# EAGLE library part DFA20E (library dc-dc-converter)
DFA20 Single-Output DC-DC Series Source: www.power-one.com / dfa20s_PCB mountable.pdf
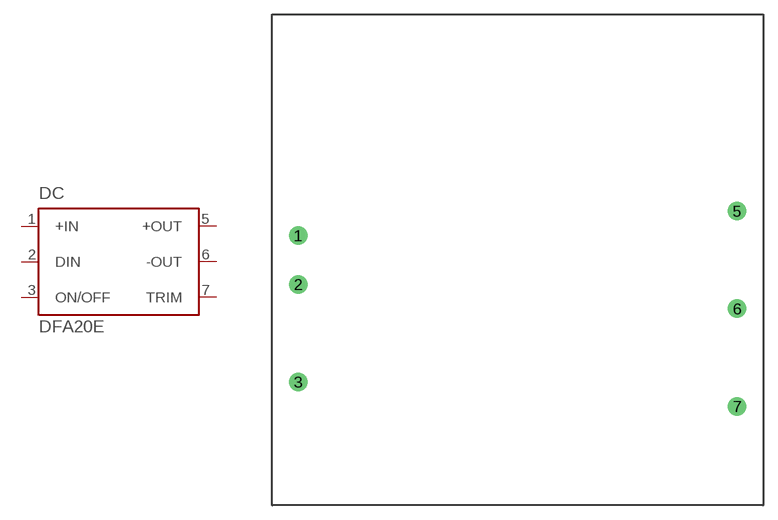
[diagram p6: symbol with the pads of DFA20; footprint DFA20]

Designator prefix DC

## DFA20E12S3.3 (OC_FARNELL: unknown; OC_NEWARK: unknown), DFA20E12S5 (OC_FARNELL: unknown; OC_NEWARK: unknown), DFA20E12S12 (OC_FARNELL: unknown; OC_NEWARK: unknown), DFA20E12S15 (OC_FARNELL: unknown; OC_NEWARK: unknown), DFA20E24S3.3 (OC_FARNELL: unknown; OC_NEWARK: unknown), DFA20E24S5 (OC_FARNELL: unknown; OC_NEWARK: unknown), DFA20E24S12 (OC_FARNELL: unknown; OC_NEWARK: unknown), DFA20E24S15 (OC_FARNELL: unknown; OC_NEWARK: unknown), DFA20E48S12 (OC_FARNELL: unknown; OC_NEWARK: unknown)  [DFA20]
1  +IN  in
2  DIN  in
3  ON/OFF  in
5  +OUT  out
6  -OUT  out
7  TRIM  in

## Footprint DFA20 (pad centres in mm)
DFA20 Single-Output DC-DC Series Source: www.power-one.com / dfa20s_PCB mountable.pdf
drill 1.2 pad 1.93 round: 1 -22.86,2.54; 2 -22.86,-2.54; 3 -22.86,-12.7; 5 22.86,5.08; 6 22.86,-5.08; 7 22.86,-15.24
